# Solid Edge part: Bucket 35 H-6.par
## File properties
Title: BUCKET 35 h 6
Author: DESYS
Template: Iso Part.par
Last saved by: i.fialdini
Revision: 54
Application: Solid Edge
Stile della faccia: Model Default
Coef. of Thermal Exp: 0.0
Thermal Conductivity: 0.0
Specific Heat: 0.0
Modulus of Elasticity: 0.0
Poisson's Ratio: 0.0
Yield Stress: 0.0
Ultimate Stress: 0.0
Elongation: 0.0
Tipo di contenuto documento: 0
Accuracy: 0.990
Document Number: 8811
Revision: 0
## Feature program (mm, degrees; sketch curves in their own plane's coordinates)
lofted protrusion "unnamed LoftedProtrusion 1"
sketch for "ScavoEstrusione_2" plane through (0, 0, 64) normal (0, 0, 1) x-axis (1, 0, 0)
  circle centre (0, 0) radius 145.5
extrude "ScavoEstrusione_2" cut finite 46 along -normal  Treatment1_DraftAngle = 13.5 deg
sketch for "ScavoEstrusione_3" plane through (0, 0, 0) normal (0, 0, -1) x-axis (0, 1, 0)
  circle centre (0, 0) radius 140
extrude "ScavoEstrusione_3" cut finite 8 along -normal
sketch for "ScavoEstrusione_5" plane through (0, 0, 18) normal (0, 0, 1) x-axis (1, 0, 0)
  circle centre (0, 0) radius 22.5
extrude "ScavoEstrusione_5" cut finite 455 along -normal
fillet "Rotondo_1" radius 10
sketch for "unnamed Protrusion 1" #1 plane through (0, 0, 8) normal (0, 0, -1) x-axis (-1, 0, 0)
  circle centre (0, 0) radius 32.5
sketch for "unnamed Protrusion 1" #2 plane through (0, 0, 8) normal (0, 0, -1) x-axis (-1, 0, 0)
  circle centre (0, 0) radius 22.5
extrude "unnamed Protrusion 1" add to key point along +normal
fillet "Rotondo_2" radius 20
fillet "Rotondo_3" radius 10
fillet "Rotondo_4" radius 3
fillet "Rotondo_6" radius 5
fillet "Rotondo_7" radius 2
sketch for "Foro_1" plane through (0, 0, 0) normal (0, 0, -1) x-axis (0, 1, 0)
  hole centre (0, 155) bore radius 5
hole "Foro_1" diameter 10 finite
mirror "unnamed Mirror 1" of "Foro_1" about plane through (0, 0, 0) normal (1, 0, 0)
hole "unnamed Hole 1" finite
fillet "Rotondo_10" radius 4
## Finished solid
Body 1: solid body, 23 faces, 23 edges, 0 vertices.
  Faces by surface: torus 10, plane 7, cylinder 5, cone 1
  Edges by curve: circle 23
Bounding box of the edges (mm; curved faces can reach further): 350.000 x 350.000 x 64.000, from (-175, -175, 0) to (175, 175, 64).
Cylindrical faces by radius (mm): R5 x2, R22.5 x1, R32.5 x1, R175 x1
Conical faces (half-angle, radius in mm at the cone's reference point): 13.5 deg R145.5 x1
Toroidal faces (ring radius, tube radius in mm): R24.5 r2 x1, R30.5 r2 x1, R32.5 r10 x1, R37.5 r5 x1, R118.6896 r20 x1, R130.202 r10 x1, R142.8512 r4 x1, R147.865 r3 x1, R172 r3 x2
Planar faces by outward normal: +z 2, -z 5
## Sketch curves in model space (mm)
line (-175, 0, 0) -> (-175, 0, 64)
line (175, 0, 64) -> (175, 0, 0)
circle centre (0, 0, 64) radius 175
circle centre (0, 0, 0) radius 175
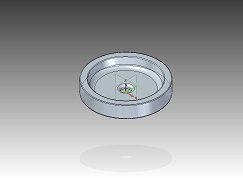
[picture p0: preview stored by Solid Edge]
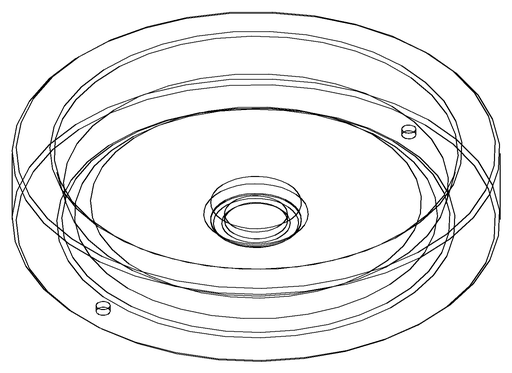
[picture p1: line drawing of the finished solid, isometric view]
